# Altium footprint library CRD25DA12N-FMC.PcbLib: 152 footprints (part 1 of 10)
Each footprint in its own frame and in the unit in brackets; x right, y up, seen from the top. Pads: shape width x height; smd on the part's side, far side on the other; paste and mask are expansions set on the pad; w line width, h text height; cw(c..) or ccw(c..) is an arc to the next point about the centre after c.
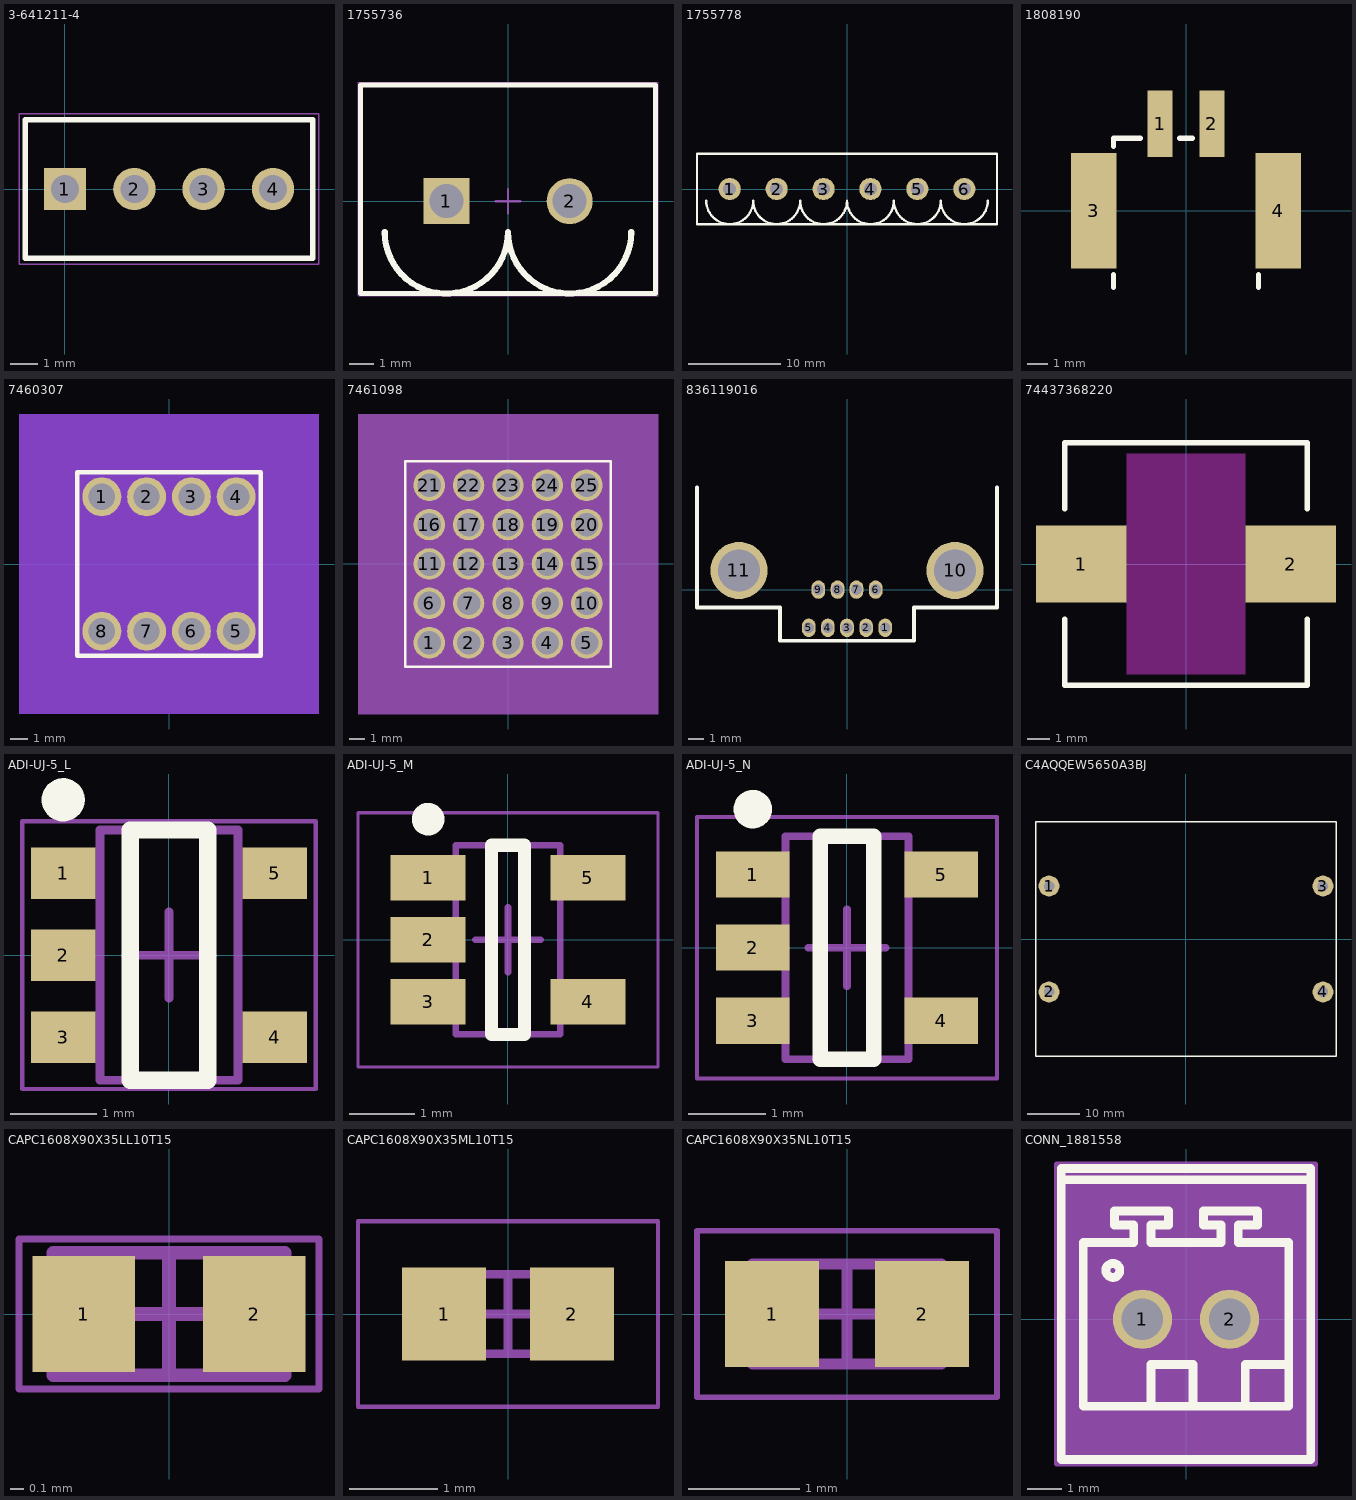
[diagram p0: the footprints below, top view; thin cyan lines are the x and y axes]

## 3-641211-4 [mm] "Connector Header Through Hole 4 position 0.100\" (2.54mm)"
height 10.03
pads (4):
  rect 1.55x1.55 hole 1.02: 1(0,0)
  round 1.55 hole 1.02: 2(2.54,0) 3(5.08,0) 4(7.62,0)
Top Overlay:
  lines w0.2: -1.46,-2.54 -1.46,2.54 9.08,2.54 9.08,-2.54 -1.46,-2.54
Mechanical 13:
  lines w0.1: -1.46,-2.54 -1.46,2.54 9.08,2.54 9.08,-2.54 -1.46,-2.54
Mechanical 15:
  lines w0.05: -1.685,-2.765 -1.685,2.765 9.305,2.765 9.305,-2.765 -1.685,-2.765
3D body "TE 3-641211-4 Color.STEP": height 10.09, standoff -3.5, extent -1.28,-2.54 8.88,2.54

## 1755736 [mm] "THD, 2-Leads, Body 12.16x8.6mm, Pitch 5.08mm"
height 12
pads (2):
  rect 1.9x1.9 hole 1.4: 1(-2.54,0)
  round 1.9 hole 1.4: 2(2.54,0)
Top Overlay:
  lines w0.2: -6.08,-3.81 -6.08,4.79 6.08,4.79 6.08,-3.81 -6.08,-3.81
  lines w0.254: -5.08,-1.27 ccw(c-2.54,-1.27) 0,-1.27 ccw(c2.54,-1.27) 5.08,-1.27
Mechanical 13:
  lines w0.1: -6.08,-3.8 6.08,-3.8 6.08,4.8 -6.08,4.8 -6.08,-3.8
Mechanical 15:
  lines w0.05: -6.18,-3.9 -6.18,4.9 6.18,4.9 6.18,-3.9 -6.18,-3.9
  lines w0.1: -0.5,0 0.5,0 ; 0,-0.5 0,0.5
3D body: height 10, standoff -3.9, extent -3.04,-0.499 -2.044,0.499
3D body: height 10, standoff -3.9, extent 2.04,-0.499 3.036,0.499
3D body: height 12, standoff 4, extent -6.079,-3.799 6.079,4.799
3D body "Phoenix Contact 1755736.stp": height 12, standoff -3.9, extent -6,-3.7 6.16,4.87

## 1755778 [mm] "TERM BLOCK HDR 6POS VERT 5.08MM"
pads (6):
  round 2.4 hole 1.4: 1(-12.7,0) 2(-7.62,0) 3(-2.54,0) 4(2.54,0) 5(7.62,0) 6(12.7,0)
Top Overlay:
  lines w0.254: -15.24,-1.27 ccw(c-12.7,-1.27) -10.16,-1.27 ccw(c-7.62,-1.27) -5.08,-1.27 ccw(c-2.54,-1.27) 0,-1.27 ccw(c2.54,-1.27) 5.08,-1.27 ccw(c7.62,-1.27) 10.16,-1.27 ccw(c12.7,-1.27) 15.24,-1.27 ; -16.24,-3.835 16.24,-3.835 16.24,3.835 -16.24,3.835 -16.24,-3.835
3D body "Phoenix Contact 1755778.stp": height 12, standoff -3.9, extent -16.24,-3.835 16.24,4.765

## 1808190 [mm]
pads (4):
  rect 1.2x3.2 smd: 1(-1.25,4.2) 2(1.25,4.2)
  rect 2.2x5.6 smd: 3(-4.45,0) 4(4.45,0)
Top Overlay:
  lines w0.254: -3.5,-3.7 -3.5,-3.1 ; -3.5,3.1 -3.5,3.5 -2.2,3.5 ; -0.3,3.5 0.3,3.5 ; 3.5,-3.7 3.5,-3.1
3D body "1808190.step": height 5, standoff 0, extent -5.4,-4 5.2,5.5

## 7460307 [mm] "8 Pin Screw Terminal, Power Tap M4 Through Hole"
pads (8):
  round 2.21 hole 1.475: 1(-3.81,3.81) 2(-1.27,3.81) 3(1.27,3.81) 4(3.81,3.81) 5(3.81,-3.81) 6(1.27,-3.81) 7(-1.27,-3.81) 8(-3.81,-3.81)
Top Layer keep-out:
  rectangle: -8.5,-8.5 8.5,8.5
Bottom Layer keep-out:
  rectangle: -8.5,-8.5 8.5,8.5
Top Overlay:
  lines w0.254: -5.2,-5.2 -5.2,5.2 5.2,5.2 5.2,-5.2 -5.2,-5.2
3D body "Wurth 7460307 - Modified.STEP": height 7, standoff -3.5, extent -4.5,-4.5 4.5,4.5

## 7461098 [mil]
pads (25):
  round 80 hole 60 mask+0: 1(-200,-200) 2(-100,-200) 3(0,-200) 4(100,-200) 5(200,-200) 6(-200,-100) 7(-100,-100) 8(0,-100) 9(100,-100) 10(200,-100) 11(-200,0) 12(-100,0) 13(0,0) 14(100,0) 15(200,0) 16(-200,100) 17(-100,100) 18(0,100) 19(100,100) 20(200,100) 21(-200,200) 22(-100,200) 23(0,200) 24(100,200) 25(200,200)
Top Overlay:
  lines w6: -261,-261.09 261,-261.09 261,260.91 -261,260.91 -261,-261.09
Mechanical 5:
  region: -381,380.91 381,380.91 381,-381.09 -381,-381.09
Mechanical 13:
  lines w1: -256,-256.09 256,-256.09 256,255.91 -256,255.91 -256,-256.09
Mechanical 15:
  region: 266,265.91 -266,265.91 -266,-266.09 266,-266.09
  lines w6: -266,-266.09 -266,265.91 266,265.91 266,-266.09 -266,-266.09
3D body: height 10, standoff 0, extent -200,-200 -190,-190
3D body "7461098_Download_STP_7461098_rev1.stp": height 610.24, standoff -137.8, extent -255.91,-255.91 255.91,255.91

## 836119016 [mm]
pads (11):
  oval 0.91x1.218 hole 0.71: 1(2.54,-2.54) 2(1.27,-2.54) 3(0,-2.54) 4(-1.27,-2.54) 5(-2.54,-2.54) 6(1.905,0) 7(0.625,0) 8(-0.625,0) 9(-1.905,0)
  round 3.79 hole 2.79: 10(7.175,1.27) 11(-7.175,1.27)
Top Overlay:
  lines w0.254: -9.965,6.8 -9.965,-1.2 -4.46,-1.2 -4.46,-3.4 4.46,-3.4 4.46,-1.2 9.965,-1.2 9.965,6.8
3D body "Molex 836119016 Color.STEP": height 7.99, standoff -2.61, extent -9.938,-3.491 9.912,11.419

## 74437368220 [mm]
pads (2):
  rect 4.1x3.5 smd: 1(-4.75,0) 2(4.75,0)
Top Layer keep-out:
  rectangle: -2.7,-5 2.7,5
Top Overlay:
  lines w0.254: -5.5,-2.5 -5.5,-5.5 5.5,-5.5 5.5,-2.5 ; -5.5,2.5 -5.5,5.5 5.5,5.5 5.5,2.5
Top Solder:
  rectangle: -2.7,-5.6 2.7,5.6
3D body "WE-LHMI_1040 (rev1).stp": height 3.7, standoff -0.1, extent -5.5,-5 5.5,5

## ADI-UJ-5_L [mm] "SOT23, 5-Leads, Body 2.9x1.6mm, Pitch 0.95mm, IPC High Density"
height 1
pads (5):
  rect 0.75x0.6 smd: 1(-1.225,0.95) 2(-1.225,0) 3(-1.225,-0.95) 4(1.225,-0.95) 5(1.225,0.95)
Top Overlay:
  circle w0.25: c-1.225,1.8 r0.125
  lines w0.2: -0.45,-1.45 -0.45,1.45 0.45,1.45 0.45,-1.45 -0.45,-1.45
Mechanical 13:
  lines w0.1: -0.8,-1.45 0.8,-1.45 0.8,1.45 -0.8,1.45 -0.8,-1.45
Mechanical 15:
  lines w0.05: -1.7,-1.55 1.7,-1.55 1.7,1.55 -1.7,1.55 -1.7,-1.55
  lines w0.1: -0.5,0 0.5,0 ; 0,-0.5 0,0.5
3D body: height 1, standoff 0, extent -0.8,-1.45 0.8,1.45

## ADI-UJ-5_M [mm] "SOT23, 5-Leads, Body 2.9x1.6mm, Pitch 0.95mm, IPC Low Density"
height 1
pads (5):
  rect 1.15x0.7 smd: 1(-1.225,0.95) 2(-1.225,0) 3(-1.225,-0.95) 4(1.225,-0.95) 5(1.225,0.95)
Top Overlay:
  circle w0.25: c-1.225,1.85 r0.125
  lines w0.2: -0.25,-1.45 -0.25,1.45 0.25,1.45 0.25,-1.45 -0.25,-1.45
Mechanical 13:
  lines w0.1: -0.8,-1.45 0.8,-1.45 0.8,1.45 -0.8,1.45 -0.8,-1.45
Mechanical 15:
  lines w0.05: -2.3,-1.95 2.3,-1.95 2.3,1.95 -2.3,1.95 -2.3,-1.95
  lines w0.1: -0.5,0 0.5,0 ; 0,-0.5 0,0.5
3D body: height 1, standoff 0, extent -0.8,-1.45 0.8,1.45

## ADI-UJ-5_N [mm] "SOT23, 5-Leads, Body 2.9x1.6mm, Pitch 0.95mm, IPC Medium Density"
height 1
pads (5):
  rect 0.95x0.6 smd: 1(-1.225,0.95) 2(-1.225,0) 3(-1.225,-0.95) 4(1.225,-0.95) 5(1.225,0.95)
Top Overlay:
  circle w0.25: c-1.225,1.8 r0.125
  lines w0.2: -0.35,-1.45 0.35,-1.45 0.35,1.45 -0.35,1.45 -0.35,-1.45
Mechanical 13:
  lines w0.1: -0.8,-1.45 -0.8,1.45 0.8,1.45 0.8,-1.45 -0.8,-1.45
Mechanical 15:
  lines w0.05: -1.95,-1.7 -1.95,1.7 1.95,1.7 1.95,-1.7 -1.95,-1.7
  lines w0.1: -0.5,0 0.5,0 ; 0,-0.5 0,0.5
3D body: height 1, standoff 0, extent -0.8,-1.45 0.8,1.45

## C4AQQEW5650A3BJ [mm] "CAP FILM 65UF 5% 1.1KVDC RAD"
pads (4):
  round 4 hole 2: 1(-26.25,10.15) 2(-26.25,-10.15) 3(26.25,10.15) 4(26.25,-10.15)
Top Overlay:
  lines w0.254: -28.75,-22.5 28.75,-22.5 28.75,22.5 -28.75,22.5 -28.75,-22.5
3D body "Kemet C4AQQEW5650A3BJ.step": height 65.4, standoff -5.9, extent -29.15,-22.755 29.15,22.75

## CAPC1608X90X35LL10T15 [mm] "Chip Capacitor, 2-Leads, Body 1.60x0.80mm, IPC High Density"
height 0.9
pads (2):
  rect 0.75x0.85 smd: 1(-0.625,0) 2(0.625,0)
Mechanical 13:
  lines w0.1: -0.85,-0.45 -0.85,0.45 0.85,0.45 0.85,-0.45 -0.85,-0.45
Mechanical 15:
  lines w0.05: -1.1,-0.55 -1.1,0.55 1.1,0.55 1.1,-0.55 -1.1,-0.55
  lines w0.1: -0.45,0 0.45,0 ; 0,-0.45 0,0.45
3D body: height 0.9, standoff 0, extent -0.5,-0.45 0.5,0.45
3D body: height 0.9, standoff 0, extent -0.85,-0.45 -0.5,0.45
3D body: height 0.9, standoff 0, extent 0.5,-0.45 0.85,0.45

## CAPC1608X90X35ML10T15 [mm] "Chip Capacitor, 2-Leads, Body 1.60x0.80mm, IPC Low Density"
height 0.9
pads (2):
  rect 0.95x1.05 smd: 1(-0.725,0) 2(0.725,0)
Mechanical 13:
  lines w0.1: -0.85,-0.45 0.85,-0.45 0.85,0.45 -0.85,0.45 -0.85,-0.45
Mechanical 15:
  lines w0.05: -1.7,-1.05 1.7,-1.05 1.7,1.05 -1.7,1.05 -1.7,-1.05
  lines w0.1: -0.45,0 0.45,0 ; 0,-0.45 0,0.45
3D body: height 0.9, standoff 0, extent 0.5,-0.45 0.85,0.45
3D body: height 0.9, standoff 0, extent -0.85,-0.45 -0.5,0.45
3D body: height 0.9, standoff 0, extent -0.5,-0.45 0.5,0.45

## CAPC1608X90X35NL10T15 [mm] "Chip Capacitor, 2-Leads, Body 1.60x0.80mm, IPC Medium Density"
height 0.9
pads (2):
  rect 0.85x0.95 smd: 1(-0.675,0) 2(0.675,0)
Mechanical 13:
  lines w0.1: -0.85,-0.45 0.85,-0.45 0.85,0.45 -0.85,0.45 -0.85,-0.45
Mechanical 15:
  lines w0.05: -1.35,-0.75 1.35,-0.75 1.35,0.75 -1.35,0.75 -1.35,-0.75
  lines w0.1: -0.45,0 0.45,0 ; 0,-0.45 0,0.45
3D body: height 0.9, standoff 0, extent 0.5,-0.45 0.85,0.45
3D body: height 0.9, standoff 0, extent -0.85,-0.45 -0.5,0.45
3D body: height 0.9, standoff 0, extent -0.5,-0.45 0.5,0.45

## CONN_1881558 [mil]
pads (2):
  round 67 / inner round 60 / far side round 67 hole 47 paste-99999 mask+0: 1(-49.21,0) 2(49.21,0)
Top Overlay:
  circle w10: c-82.68,55.12 r7.87
  lines w10: -140.98,157.48 138.54,157.48 ; -80.71,106.3 -80.71,122.05 ; -78.74,106.3 -59.06,106.3 -59.06,86.61 ; -78.74,122.05 -19.68,122.05 -19.68,106.3 -39.37,106.3 -39.37,86.61 0,86.61 39.37,86.61 39.37,106.3 19.68,106.3 19.68,122.05 78.74,122.05 ; -61.02,86.61 -116.14,86.61 -116.14,-98.43 7.87,-98.43 7.87,-51.18 -39.37,-51.18 -39.37,-97.44 ; 0,-98.43 116.14,-98.43 116.14,86.61 61.02,86.61 ; 59.06,86.61 59.06,106.3 78.74,106.3 ; 66.93,-96.46 66.93,-51.18 113.19,-51.18 ; 80.71,106.3 80.71,122.05 ; -141,-158.65 -141,170.35 141,170.35 141,-158.65 -141,-158.65
Mechanical 13:
  circle w20: c-49.21,-75 r15
  lines w1: -136,-153.65 -136,165.35 136,165.35 136,-153.65 -136,-153.65
Mechanical 15:
  region: 146,175.35 -146,175.35 -146,-163.65 146,-163.65
  lines w6: -146,-163.65 146,-163.65 146,175.35 -146,175.35 -146,-163.65
3D body "pxc_1881558_01_MCV-0-5-2-G-2-5_3D.stp": height 397.64, standoff -137.8, extent -135.83,-153.54 135.83,165.35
